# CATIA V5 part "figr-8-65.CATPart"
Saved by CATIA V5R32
Part number: Part1
Bounding box of the stored display mesh (mm): x -53.439 to 53.439, y -63.41 to 103.633, z -17.5 to 34.5
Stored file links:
  D:\PROJECTS\Project 2022\CATIA V5 6R 2022\Resources\Part Files\c08_catia_v5_6r2022_prt\figr-8-65.CATPart
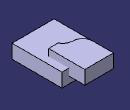
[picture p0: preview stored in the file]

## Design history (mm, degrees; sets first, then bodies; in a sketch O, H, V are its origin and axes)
Body1 (main body)
  Sketch1 on xy-plane, origin (0, 0, 0), H (1, 0, 0), V (0, 1, 0)
    line L1 (-53.4395, 63.4095) -> (53.4395, 63.4095)
    line L2 (53.4395, 63.4095) -> (53.4395, -63.4095)
    line L3 (53.4395, -63.4095) -> (-53.4395, -63.4095)
    line L4 (-53.4395, -63.4095) -> (-53.4395, 63.4095)
    axis line L5 (53.4395, -63.4095) -> (-53.4395, 63.4095)
    horizontal: L1 H, L3 H
    vertical: L2 V, L4 V
    midpoint: O L5
  Pad1: profile Sketch1, direction (0, 0, 1), length 17.5, mirrored extent
Body2
  Sketch2 on xy-plane, origin (0, 0, 0), H (1, 0, 0), V (0, 1, 0)
    line L1 (-36.9238, 103.6333) -> (-36.9238, 51.4035)
    arc A1 centre (-11.4307, 51.4035) radius 25.4931 from (-36.9238, 51.4035) to (-11.4307, 25.9104) ccw
    arc A2 centre (-11.4307, 0.4172) radius 25.4931 from (-11.4307, 25.9104) to (11.4981, 11.5602) cw
    line L2 (11.4981, 11.5602) -> (35.6176, 11.5602)
    line L3 (35.6176, 11.5602) -> (35.6176, 103.6333)
    line L4 (35.6176, 103.6333) -> (-36.9238, 103.6333)
    vertical: L1 V, L3 V
    tangency: A1 L1, A2 L1, A2 A1
    horizontal: L2 H, L4 H
  Pad2: profile Sketch2, direction (0, 0, 1), length 34.5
